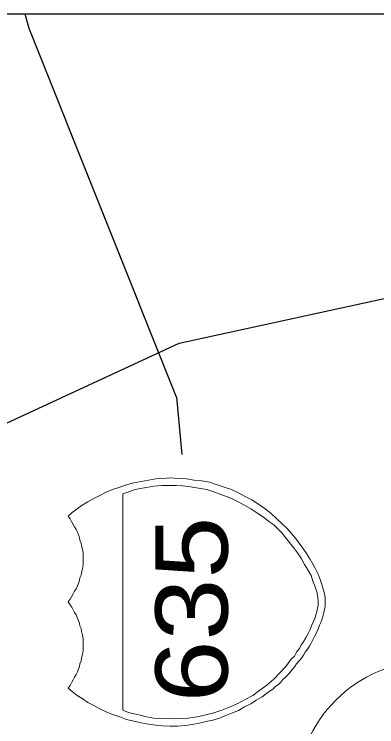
# Model space of a CAD drawing. Extents: x 2363323 to 2367082, y 6956018 to 6980837.
# Drawn here: x 2365901.2 to 2365926.7, y 6957032.4 to 6957082.5 of the extents above; entities that cross this region are included whole.
import ezdxf

# ---------------------------------------------------------------- set-up
doc = ezdxf.new("R2010")
doc.units = 0
doc.header["$LTSCALE"] = 4.1
doc.layers.add('62', color=7, linetype='Continuous', lineweight=13)
doc.layers.add('63', color=7, linetype='Continuous', lineweight=13)

msp = doc.modelspace()

# ---------------------------------------------------------------- linework, layer by layer
at = {"layer": '62', "lineweight": 25}
msp.add_line((2365912.618, 6957055.568), (2365912.978, 6957051.542), dxfattribs=at)
for points in [[(2365769.011, 6956632.956), (2366234.284, 6956632.956), (2366234.284, 6957082.548), (2365769.009, 6957082.548)], [(2365892.929, 6957050.214), (2365912.797, 6957059.392), (2365948.936, 6957067.246), (2365975.307, 6957082.548)], [(2365912.618, 6957055.568), (2365902.223, 6957081.537), (2365901.931, 6957082.548)]]:
    msp.add_lwpolyline(points, dxfattribs=at)
at = {"layer": '62'}
for points in [[(2365905.417, 6957041.912), (2365905.529, 6957042.09), (2365905.619, 6957042.292), (2365905.687, 6957042.45), (2365905.778, 6957042.675), (2365905.799, 6957042.855), (2365905.889, 6957043.036), (2365905.911, 6957043.215), (2365905.957, 6957043.418), (2365906.001, 6957043.598), (2365906.024, 6957043.802), (2365906.024, 6957043.982), (2365906.024, 6957044.182), (2365906.025, 6957044.362), (2365906.024, 6957044.565), (2365906.003, 6957044.769), (2365905.958, 6957044.948), (2365905.913, 6957045.105), (2365905.889, 6957045.308), (2365905.799, 6957045.51), (2365905.777, 6957045.69), (2365905.688, 6957045.892), (2365905.619, 6957046.072), (2365905.529, 6957046.252), (2365905.417, 6957046.456), (2365905.328, 6957046.614), (2365905.214, 6957046.815), (2365905.103, 6957047.018), (2365904.967, 6957047.198), (2365905.261, 6957047.466), (2365905.597, 6957047.715), (2365905.957, 6957047.962), (2365906.363, 6957048.21), (2365906.768, 6957048.435), (2365907.194, 6957048.66), (2365907.645, 6957048.885), (2365908.095, 6957049.065), (2365908.613, 6957049.246), (2365909.084, 6957049.402), (2365909.603, 6957049.538), (2365910.121, 6957049.65), (2365910.637, 6957049.742), (2365911.154, 6957049.83), (2365911.651, 6957049.852), (2365912.168, 6957049.898), (2365912.731, 6957049.852), (2365913.314, 6957049.832), (2365913.854, 6957049.74), (2365914.394, 6957049.695), (2365914.934, 6957049.584), (2365915.474, 6957049.402), (2365915.971, 6957049.245), (2365916.487, 6957049.065), (2365916.983, 6957048.84), (2365917.455, 6957048.592), (2365917.929, 6957048.344), (2365918.379, 6957048.052), (2365918.851, 6957047.715), (2365919.279, 6957047.376), (2365919.685, 6957047.018), (2365920.112, 6957046.612), (2365920.405, 6957046.322), (2365920.697, 6957046.005), (2365920.989, 6957045.645), (2365921.259, 6957045.308), (2365921.509, 6957044.946), (2365921.777, 6957044.565), (2365922.002, 6957044.182), (2365922.227, 6957043.822), (2365922.405, 6957043.485), (2365922.587, 6957043.102), (2365922.746, 6957042.744), (2365922.857, 6957042.382), (2365922.949, 6957042.068), (2365923.037, 6957041.752), (2365923.082, 6957041.436), (2365923.083, 6957041.168)], [(2365923.083, 6957041.168), (2365923.082, 6957040.986), (2365923.082, 6957040.827), (2365923.039, 6957040.648), (2365923.015, 6957040.491), (2365922.969, 6957040.311), (2365922.925, 6957040.131), (2365922.857, 6957039.906), (2365922.789, 6957039.702), (2365922.699, 6957039.525), (2365922.609, 6957039.321), (2365922.521, 6957039.096), (2365922.431, 6957038.895), (2365922.317, 6957038.668), (2365922.227, 6957038.488), (2365922.092, 6957038.264), (2365921.979, 6957038.038), (2365921.846, 6957037.838), (2365921.689, 6957037.612), (2365921.552, 6957037.41), (2365921.417, 6957037.206), (2365921.261, 6957037.005), (2365921.079, 6957036.801), (2365920.946, 6957036.6), (2365920.787, 6957036.417), (2365920.631, 6957036.216), (2365920.472, 6957036.038), (2365920.293, 6957035.856), (2365920.112, 6957035.698), (2365919.955, 6957035.496), (2365919.799, 6957035.338), (2365919.619, 6957035.226), (2365919.415, 6957035.048), (2365919.056, 6957034.776), (2365918.648, 6957034.484), (2365918.221, 6957034.236), (2365917.838, 6957033.988), (2365917.409, 6957033.762), (2365916.981, 6957033.516), (2365916.553, 6957033.336), (2365916.081, 6957033.156), (2365915.631, 6957032.974), (2365915.161, 6957032.838), (2365914.688, 6957032.727), (2365914.215, 6957032.614), (2365913.721, 6957032.526), (2365913.225, 6957032.457), (2365912.685, 6957032.412), (2365912.167, 6957032.412), (2365911.649, 6957032.434), (2365911.154, 6957032.48), (2365910.637, 6957032.547), (2365910.119, 6957032.637), (2365909.601, 6957032.75), (2365909.084, 6957032.884), (2365908.613, 6957033.064), (2365908.094, 6957033.222), (2365907.644, 6957033.428), (2365907.194, 6957033.628), (2365906.767, 6957033.854), (2365906.363, 6957034.078), (2365905.957, 6957034.348), (2365905.598, 6957034.574), (2365905.261, 6957034.844), (2365904.968, 6957035.091), (2365905.103, 6957035.27), (2365905.215, 6957035.498), (2365905.328, 6957035.676), (2365905.415, 6957035.856), (2365905.529, 6957036.058), (2365905.619, 6957036.24), (2365905.687, 6957036.442), (2365905.777, 6957036.622), (2365905.801, 6957036.801), (2365905.891, 6957037.004), (2365905.911, 6957037.184), (2365905.957, 6957037.386), (2365906.001, 6957037.588), (2365906.025, 6957037.746), (2365906.024, 6957037.926), (2365906.024, 6957038.151), (2365906.024, 6957038.331), (2365906.025, 6957038.511), (2365906.001, 6957038.714), (2365905.957, 6957038.895), (2365905.911, 6957039.075), (2365905.891, 6957039.276), (2365905.801, 6957039.478), (2365905.777, 6957039.658), (2365905.687, 6957039.838), (2365905.621, 6957040.02), (2365905.531, 6957040.244), (2365905.417, 6957040.424), (2365905.327, 6957040.604), (2365905.215, 6957040.785), (2365905.101, 6957040.965), (2365904.967, 6957041.166), (2365905.101, 6957041.346), (2365905.214, 6957041.526), (2365905.327, 6957041.728), (2365905.417, 6957041.912)]]:
    msp.add_lwpolyline(points, dxfattribs=at)
msp.add_lwpolyline([(2365908.815, 6957048.771), (2365908.815, 6957033.538), (2365909.041, 6957033.448), (2365909.311, 6957033.358), (2365909.625, 6957033.267), (2365910.051, 6957033.177), (2365910.503, 6957033.064), (2365910.997, 6957032.974), (2365911.559, 6957032.952), (2365912.167, 6957032.931), (2365912.798, 6957032.952), (2365913.428, 6957032.974), (2365914.058, 6957033.064), (2365914.664, 6957033.2), (2365915.249, 6957033.358), (2365915.811, 6957033.538), (2365916.397, 6957033.764), (2365916.937, 6957034.011), (2365917.454, 6957034.281), (2365917.995, 6957034.575), (2365918.491, 6957034.934), (2365918.987, 6957035.294), (2365919.459, 6957035.721), (2365919.887, 6957036.172), (2365920.315, 6957036.62), (2365920.697, 6957037.116), (2365920.922, 6957037.342), (2365921.079, 6957037.611), (2365921.259, 6957037.858), (2365921.417, 6957038.152), (2365921.576, 6957038.398), (2365921.755, 6957038.668), (2365921.889, 6957038.938), (2365922.026, 6957039.208), (2365922.137, 6957039.478), (2365922.249, 6957039.726), (2365922.362, 6957039.996), (2365922.429, 6957040.244), (2365922.499, 6957040.491), (2365922.542, 6957040.716), (2365922.587, 6957040.94), (2365922.587, 6957041.166), (2365922.565, 6957041.482), (2365922.499, 6957041.865), (2365922.385, 6957042.225), (2365922.227, 6957042.63), (2365922.092, 6957043.012), (2365921.867, 6957043.418), (2365921.642, 6957043.8), (2365921.419, 6957044.205), (2365921.149, 6957044.61), (2365920.855, 6957044.991), (2365920.586, 6957045.352), (2365920.292, 6957045.688), (2365920.023, 6957046.028), (2365919.729, 6957046.32), (2365919.461, 6957046.59), (2365919.189, 6957046.77), (2365918.739, 6957047.132), (2365918.265, 6957047.422), (2365917.838, 6957047.715), (2365917.364, 6957047.985), (2365916.914, 6957048.232), (2365916.488, 6957048.436), (2365916.059, 6957048.615), (2365915.609, 6957048.774), (2365915.161, 6957048.928), (2365914.754, 6957049.065), (2365914.304, 6957049.155), (2365913.878, 6957049.224), (2365913.449, 6957049.29), (2365913.021, 6957049.335), (2365912.594, 6957049.358), (2365912.167, 6957049.358), (2365911.561, 6957049.359), (2365910.998, 6957049.314), (2365910.503, 6957049.222), (2365910.053, 6957049.155), (2365909.624, 6957049.042), (2365909.311, 6957048.93), (2365909.041, 6957048.842)], close=True, dxfattribs=at)
msp.add_circle((2365930.46, 6957027.623), 9.364, dxfattribs=at)
at = {"layer": '63', "lineweight": 25}
msp.add_line((2365912.618, 6957055.568), (2365912.978, 6957051.542), dxfattribs=at)
for points in [[(2365769.011, 6956632.956), (2366234.284, 6956632.956), (2366234.284, 6957082.548), (2365769.009, 6957082.548)], [(2365892.929, 6957050.214), (2365912.797, 6957059.392), (2365948.936, 6957067.246), (2365975.307, 6957082.548)], [(2365912.618, 6957055.568), (2365902.223, 6957081.537), (2365901.931, 6957082.548)]]:
    msp.add_lwpolyline(points, dxfattribs=at)
at = {"layer": '63'}
for points in [[(2365905.417, 6957041.912), (2365905.529, 6957042.09), (2365905.619, 6957042.292), (2365905.687, 6957042.45), (2365905.778, 6957042.675), (2365905.799, 6957042.855), (2365905.889, 6957043.036), (2365905.911, 6957043.215), (2365905.957, 6957043.418), (2365906.001, 6957043.598), (2365906.024, 6957043.802), (2365906.024, 6957043.982), (2365906.024, 6957044.182), (2365906.025, 6957044.362), (2365906.024, 6957044.565), (2365906.003, 6957044.769), (2365905.958, 6957044.948), (2365905.913, 6957045.105), (2365905.889, 6957045.308), (2365905.799, 6957045.51), (2365905.777, 6957045.69), (2365905.688, 6957045.892), (2365905.619, 6957046.072), (2365905.529, 6957046.252), (2365905.417, 6957046.456), (2365905.328, 6957046.614), (2365905.214, 6957046.815), (2365905.103, 6957047.018), (2365904.967, 6957047.198), (2365905.261, 6957047.466), (2365905.597, 6957047.715), (2365905.957, 6957047.962), (2365906.363, 6957048.21), (2365906.768, 6957048.435), (2365907.194, 6957048.66), (2365907.645, 6957048.885), (2365908.095, 6957049.065), (2365908.613, 6957049.246), (2365909.084, 6957049.402), (2365909.603, 6957049.538), (2365910.121, 6957049.65), (2365910.637, 6957049.742), (2365911.154, 6957049.83), (2365911.651, 6957049.852), (2365912.168, 6957049.898), (2365912.731, 6957049.852), (2365913.314, 6957049.832), (2365913.854, 6957049.74), (2365914.394, 6957049.695), (2365914.934, 6957049.584), (2365915.474, 6957049.402), (2365915.971, 6957049.245), (2365916.487, 6957049.065), (2365916.983, 6957048.84), (2365917.455, 6957048.592), (2365917.929, 6957048.344), (2365918.379, 6957048.052), (2365918.851, 6957047.715), (2365919.279, 6957047.376), (2365919.685, 6957047.018), (2365920.112, 6957046.612), (2365920.405, 6957046.322), (2365920.697, 6957046.005), (2365920.989, 6957045.645), (2365921.259, 6957045.308), (2365921.509, 6957044.946), (2365921.777, 6957044.565), (2365922.002, 6957044.182), (2365922.227, 6957043.822), (2365922.405, 6957043.485), (2365922.587, 6957043.102), (2365922.746, 6957042.744), (2365922.857, 6957042.382), (2365922.949, 6957042.068), (2365923.037, 6957041.752), (2365923.082, 6957041.436), (2365923.083, 6957041.168)], [(2365923.083, 6957041.168), (2365923.082, 6957040.986), (2365923.082, 6957040.827), (2365923.039, 6957040.648), (2365923.015, 6957040.491), (2365922.969, 6957040.311), (2365922.925, 6957040.131), (2365922.857, 6957039.906), (2365922.789, 6957039.702), (2365922.699, 6957039.525), (2365922.609, 6957039.321), (2365922.521, 6957039.096), (2365922.431, 6957038.895), (2365922.317, 6957038.668), (2365922.227, 6957038.488), (2365922.092, 6957038.264), (2365921.979, 6957038.038), (2365921.846, 6957037.838), (2365921.689, 6957037.612), (2365921.552, 6957037.41), (2365921.417, 6957037.206), (2365921.261, 6957037.005), (2365921.079, 6957036.801), (2365920.946, 6957036.6), (2365920.787, 6957036.417), (2365920.631, 6957036.216), (2365920.472, 6957036.038), (2365920.293, 6957035.856), (2365920.112, 6957035.698), (2365919.955, 6957035.496), (2365919.799, 6957035.338), (2365919.619, 6957035.226), (2365919.415, 6957035.048), (2365919.056, 6957034.776), (2365918.648, 6957034.484), (2365918.221, 6957034.236), (2365917.838, 6957033.988), (2365917.409, 6957033.762), (2365916.981, 6957033.516), (2365916.553, 6957033.336), (2365916.081, 6957033.156), (2365915.631, 6957032.974), (2365915.161, 6957032.838), (2365914.688, 6957032.727), (2365914.215, 6957032.614), (2365913.721, 6957032.526), (2365913.225, 6957032.457), (2365912.685, 6957032.412), (2365912.167, 6957032.412), (2365911.649, 6957032.434), (2365911.154, 6957032.48), (2365910.637, 6957032.547), (2365910.119, 6957032.637), (2365909.601, 6957032.75), (2365909.084, 6957032.884), (2365908.613, 6957033.064), (2365908.094, 6957033.222), (2365907.644, 6957033.428), (2365907.194, 6957033.628), (2365906.767, 6957033.854), (2365906.363, 6957034.078), (2365905.957, 6957034.348), (2365905.598, 6957034.574), (2365905.261, 6957034.844), (2365904.968, 6957035.091), (2365905.103, 6957035.27), (2365905.215, 6957035.498), (2365905.328, 6957035.676), (2365905.415, 6957035.856), (2365905.529, 6957036.058), (2365905.619, 6957036.24), (2365905.687, 6957036.442), (2365905.777, 6957036.622), (2365905.801, 6957036.801), (2365905.891, 6957037.004), (2365905.911, 6957037.184), (2365905.957, 6957037.386), (2365906.001, 6957037.588), (2365906.025, 6957037.746), (2365906.024, 6957037.926), (2365906.024, 6957038.151), (2365906.024, 6957038.331), (2365906.025, 6957038.511), (2365906.001, 6957038.714), (2365905.957, 6957038.895), (2365905.911, 6957039.075), (2365905.891, 6957039.276), (2365905.801, 6957039.478), (2365905.777, 6957039.658), (2365905.687, 6957039.838), (2365905.621, 6957040.02), (2365905.531, 6957040.244), (2365905.417, 6957040.424), (2365905.327, 6957040.604), (2365905.215, 6957040.785), (2365905.101, 6957040.965), (2365904.967, 6957041.166), (2365905.101, 6957041.346), (2365905.214, 6957041.526), (2365905.327, 6957041.728), (2365905.417, 6957041.912)]]:
    msp.add_lwpolyline(points, dxfattribs=at)
msp.add_lwpolyline([(2365908.815, 6957048.771), (2365908.815, 6957033.538), (2365909.041, 6957033.448), (2365909.311, 6957033.358), (2365909.625, 6957033.267), (2365910.051, 6957033.177), (2365910.503, 6957033.064), (2365910.997, 6957032.974), (2365911.559, 6957032.952), (2365912.167, 6957032.931), (2365912.798, 6957032.952), (2365913.428, 6957032.974), (2365914.058, 6957033.064), (2365914.664, 6957033.2), (2365915.249, 6957033.358), (2365915.811, 6957033.538), (2365916.397, 6957033.764), (2365916.937, 6957034.011), (2365917.454, 6957034.281), (2365917.995, 6957034.575), (2365918.491, 6957034.934), (2365918.987, 6957035.294), (2365919.459, 6957035.721), (2365919.887, 6957036.172), (2365920.315, 6957036.62), (2365920.697, 6957037.116), (2365920.922, 6957037.342), (2365921.079, 6957037.611), (2365921.259, 6957037.858), (2365921.417, 6957038.152), (2365921.576, 6957038.398), (2365921.755, 6957038.668), (2365921.889, 6957038.938), (2365922.026, 6957039.208), (2365922.137, 6957039.478), (2365922.249, 6957039.726), (2365922.362, 6957039.996), (2365922.429, 6957040.244), (2365922.499, 6957040.491), (2365922.542, 6957040.716), (2365922.587, 6957040.94), (2365922.587, 6957041.166), (2365922.565, 6957041.482), (2365922.499, 6957041.865), (2365922.385, 6957042.225), (2365922.227, 6957042.63), (2365922.092, 6957043.012), (2365921.867, 6957043.418), (2365921.642, 6957043.8), (2365921.419, 6957044.205), (2365921.149, 6957044.61), (2365920.855, 6957044.991), (2365920.586, 6957045.352), (2365920.292, 6957045.688), (2365920.023, 6957046.028), (2365919.729, 6957046.32), (2365919.461, 6957046.59), (2365919.189, 6957046.77), (2365918.739, 6957047.132), (2365918.265, 6957047.422), (2365917.838, 6957047.715), (2365917.364, 6957047.985), (2365916.914, 6957048.232), (2365916.488, 6957048.436), (2365916.059, 6957048.615), (2365915.609, 6957048.774), (2365915.161, 6957048.928), (2365914.754, 6957049.065), (2365914.304, 6957049.155), (2365913.878, 6957049.224), (2365913.449, 6957049.29), (2365913.021, 6957049.335), (2365912.594, 6957049.358), (2365912.167, 6957049.358), (2365911.561, 6957049.359), (2365910.998, 6957049.314), (2365910.503, 6957049.222), (2365910.053, 6957049.155), (2365909.624, 6957049.042), (2365909.311, 6957048.93), (2365909.041, 6957048.842)], close=True, dxfattribs=at)
msp.add_circle((2365930.46, 6957027.623), 9.364, dxfattribs=at)

# ---------------------------------------------------------------- texts
at = {"layer": '62', "width": 1.15}
msp.add_text('635', height=5.099, rotation=90, dxfattribs=at).set_placement((2365916.216, 6957034.079))
at = {"layer": '63', "width": 1.15}
msp.add_text('635', height=5.099, rotation=90, dxfattribs=at).set_placement((2365916.216, 6957034.079))

doc.saveas('drawing.dxf')
